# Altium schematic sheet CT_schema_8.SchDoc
size 402 x 220 mm
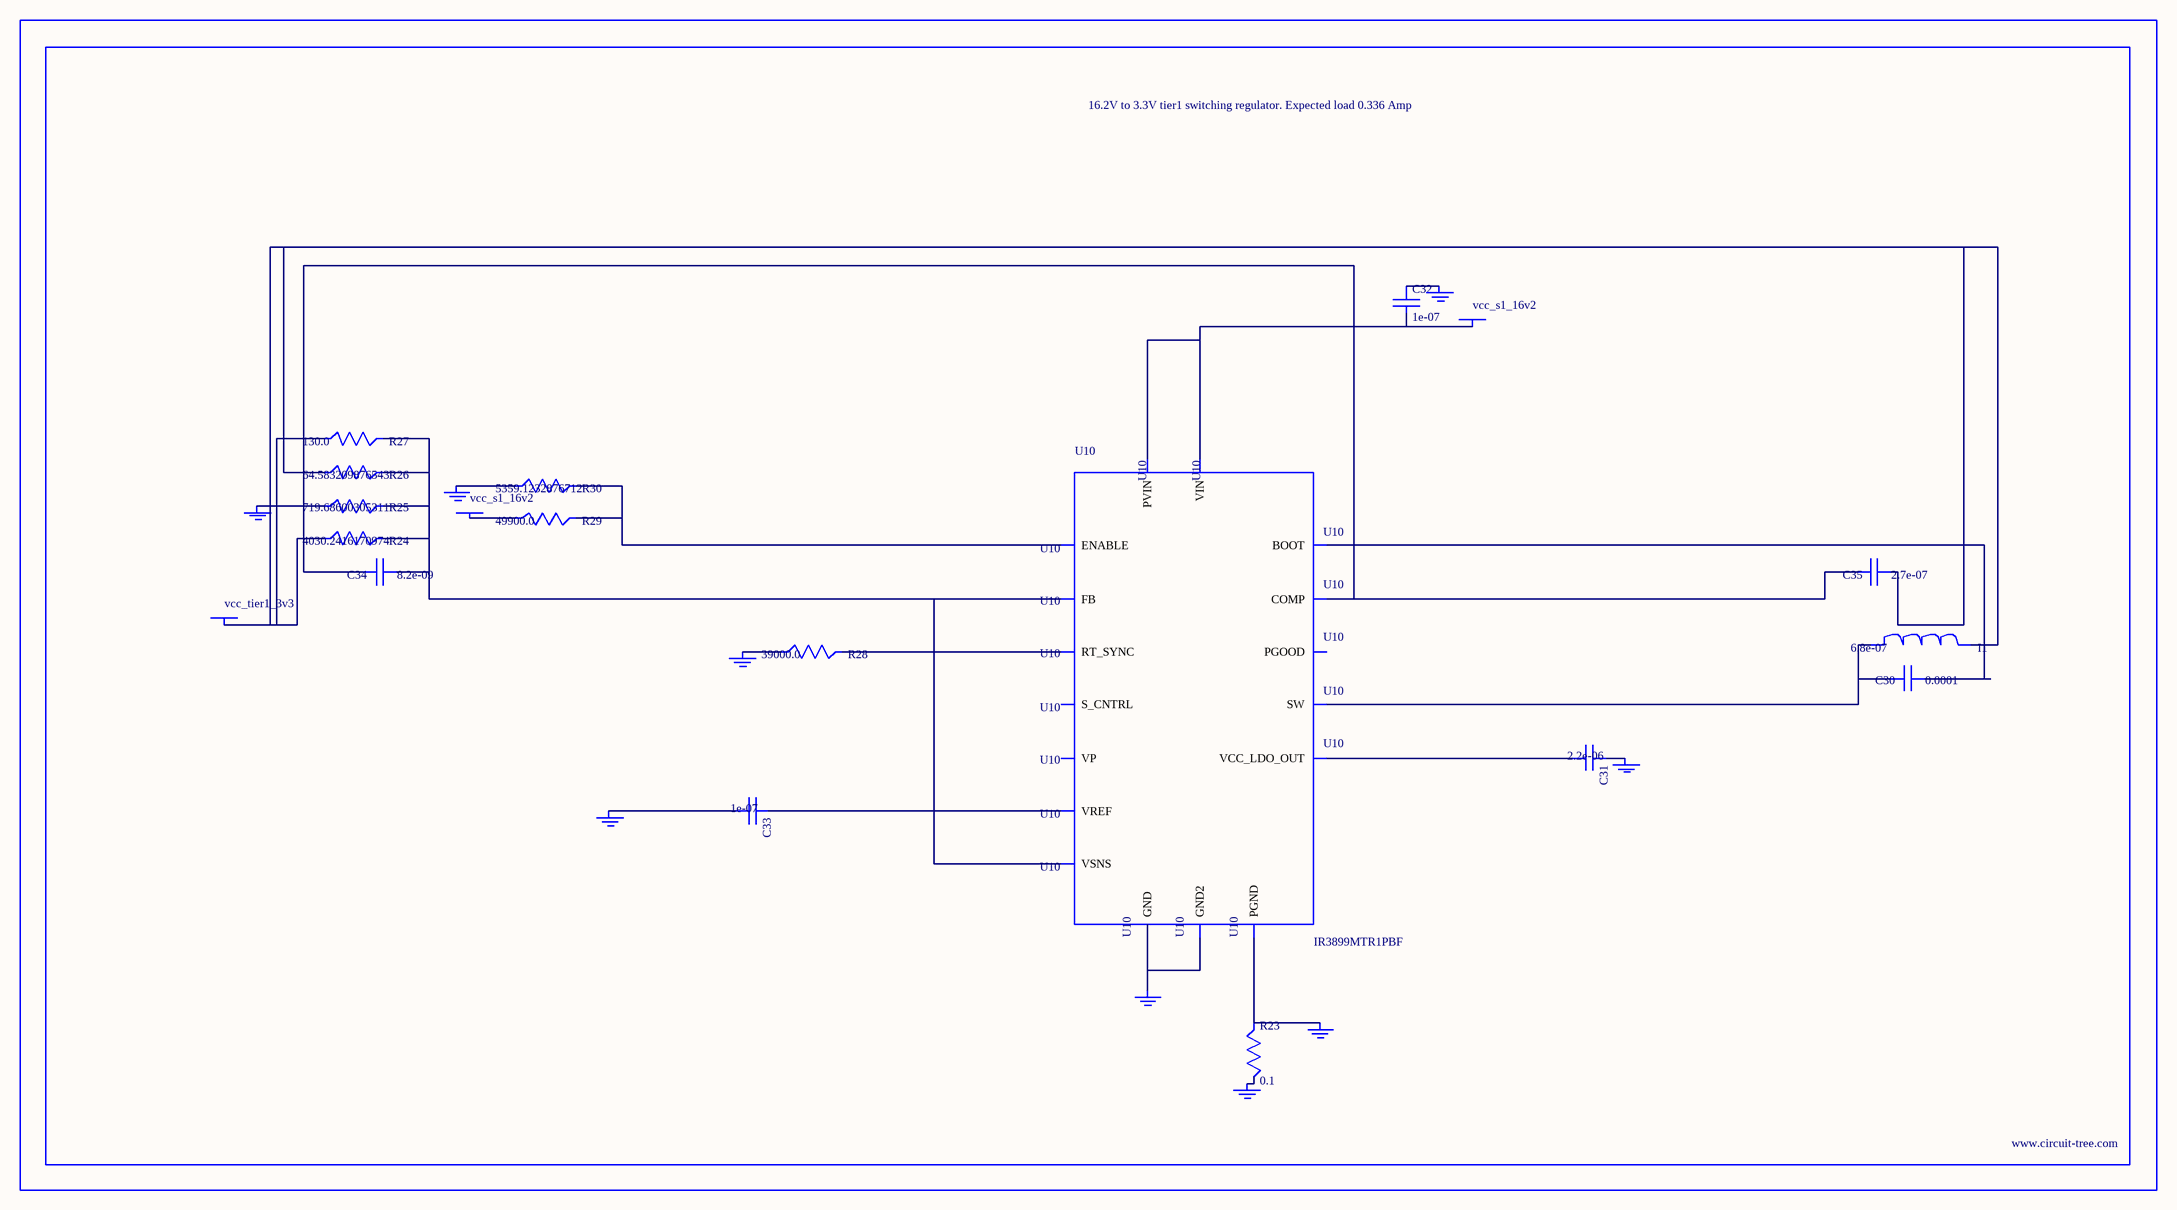
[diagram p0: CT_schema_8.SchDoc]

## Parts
BORDER7  (no value)
C30  0.0001  [C1210]
C31  2.2e-06  [C0603]
C32  1e-07  [C0402]
C33  1e-07  [C0402]
C34  8.2e-09  [C0402]
C35  2.7e-07  [C0603]
GND_INSTANCE_7_0  (no value)
GND_INSTANCE_7_1  (no value)
GND_INSTANCE_7_2  (no value)
GND_INSTANCE_7_3  (no value)
GND_INSTANCE_7_4  (no value)
GND_INSTANCE_7_5  (no value)
GND_INSTANCE_7_6  (no value)
GND_INSTANCE_7_7  (no value)
GND_INSTANCE_7_8  (no value)
I1  6.8e-07  [IND25X25CZ]
POWER_INSTANCE_7_0  vcc_s1_16v2
POWER_INSTANCE_7_1  vcc_s1_16v2
POWER_INSTANCE_7_2  vcc_tier1_3v3
R23  0.1  [R0603]
R24  4030.2416170974  [R0603]
R25  719.68600305311  [R0603]
R26  64.583209876543  [R0603]
R27  130.0  [R0603]
R28  39000.0  [R0603]
R29  49900.0  [R0603]
R30  5359.1232876712  [R0603]
U10  IR3899MTR1PBF  [IR3899MTR1PBF]

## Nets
NetC30_1: C30.1 U10.14(BOOT)
NetC30_2: C30.2 I1.1 U10.12(SW)
NetC31_1: C31.1 GND_INSTANCE_7_4.0(GND)
NetC31_2: C31.2 U10.10(VCC_LDO_OUT)
NetC32_1: C32.1 GND_INSTANCE_7_3.0(GND)
NetC32_2: C32.2 POWER_INSTANCE_7_0.0(PWR) U10.9(VIN) U10.13(PVIN)
NetC33_1: C33.1 U10.2(VREF)
NetC33_2: C33.2 GND_INSTANCE_7_1.0(GND)
NetC34_1: C34.1 R24.2 R25.2 R26.2 R27.2 U10.1(FB) U10.8(VSNS)
NetC34_2: C34.2 C35.2 U10.3(COMP)
NetC35_1: C35.1 I1.2 POWER_INSTANCE_7_2.0(PWR) R24.1 R26.1 R27.1
NetGND_INSTANCE_7_0_0: GND_INSTANCE_7_0.0(GND) R25.1
NetGND_INSTANCE_7_2_0: GND_INSTANCE_7_2.0(GND) R28.1
NetGND_INSTANCE_7_5_0: GND_INSTANCE_7_5.0(GND) R23.2
NetGND_INSTANCE_7_6_0: GND_INSTANCE_7_6.0(GND) R23.1 U10.11(PGND)
NetGND_INSTANCE_7_7_0: GND_INSTANCE_7_7.0(GND) R30.1
NetGND_INSTANCE_7_8_0: GND_INSTANCE_7_8.0(GND) U10.4(GND) U10.17(GND2)
NetPOWER_INSTANCE_7_1_0: POWER_INSTANCE_7_1.0(PWR) R29.1
NetR28_2: R28.2 U10.5(RT_SYNC)
NetR29_2: R29.2 R30.2 U10.15(ENABLE)

Not connected (* = marked no-connect by the designer): U10 6(S_CNTRL) 7(PGOOD) 16(VP)

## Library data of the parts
BORDER7 = BORDER_PAGE7
C30 = GRM32ER61A107ME20L
C31 = C0603C225K8RACTU
C32 C33 = C0402C104K3RACTU
C34 = C0402C822K3RAC
C35 = C0603C274K3RAC
GND_INSTANCE_7_0-GND_INSTANCE_7_8 = GND
I1 = IHLP2525CZERR68M01
POWER_INSTANCE_7_0-POWER_INSTANCE_7_2 = PWR
R23 = ERJ-3RSFR10V
R24 = R24
R25 = R25
R26 = R26
R27 = RC0603JR-07130RL
R28 = RC0603JR-0739KL
R29 = RC0603FR-0749K9
R30 = R30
